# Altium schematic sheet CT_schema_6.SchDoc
size 296 x 239 mm
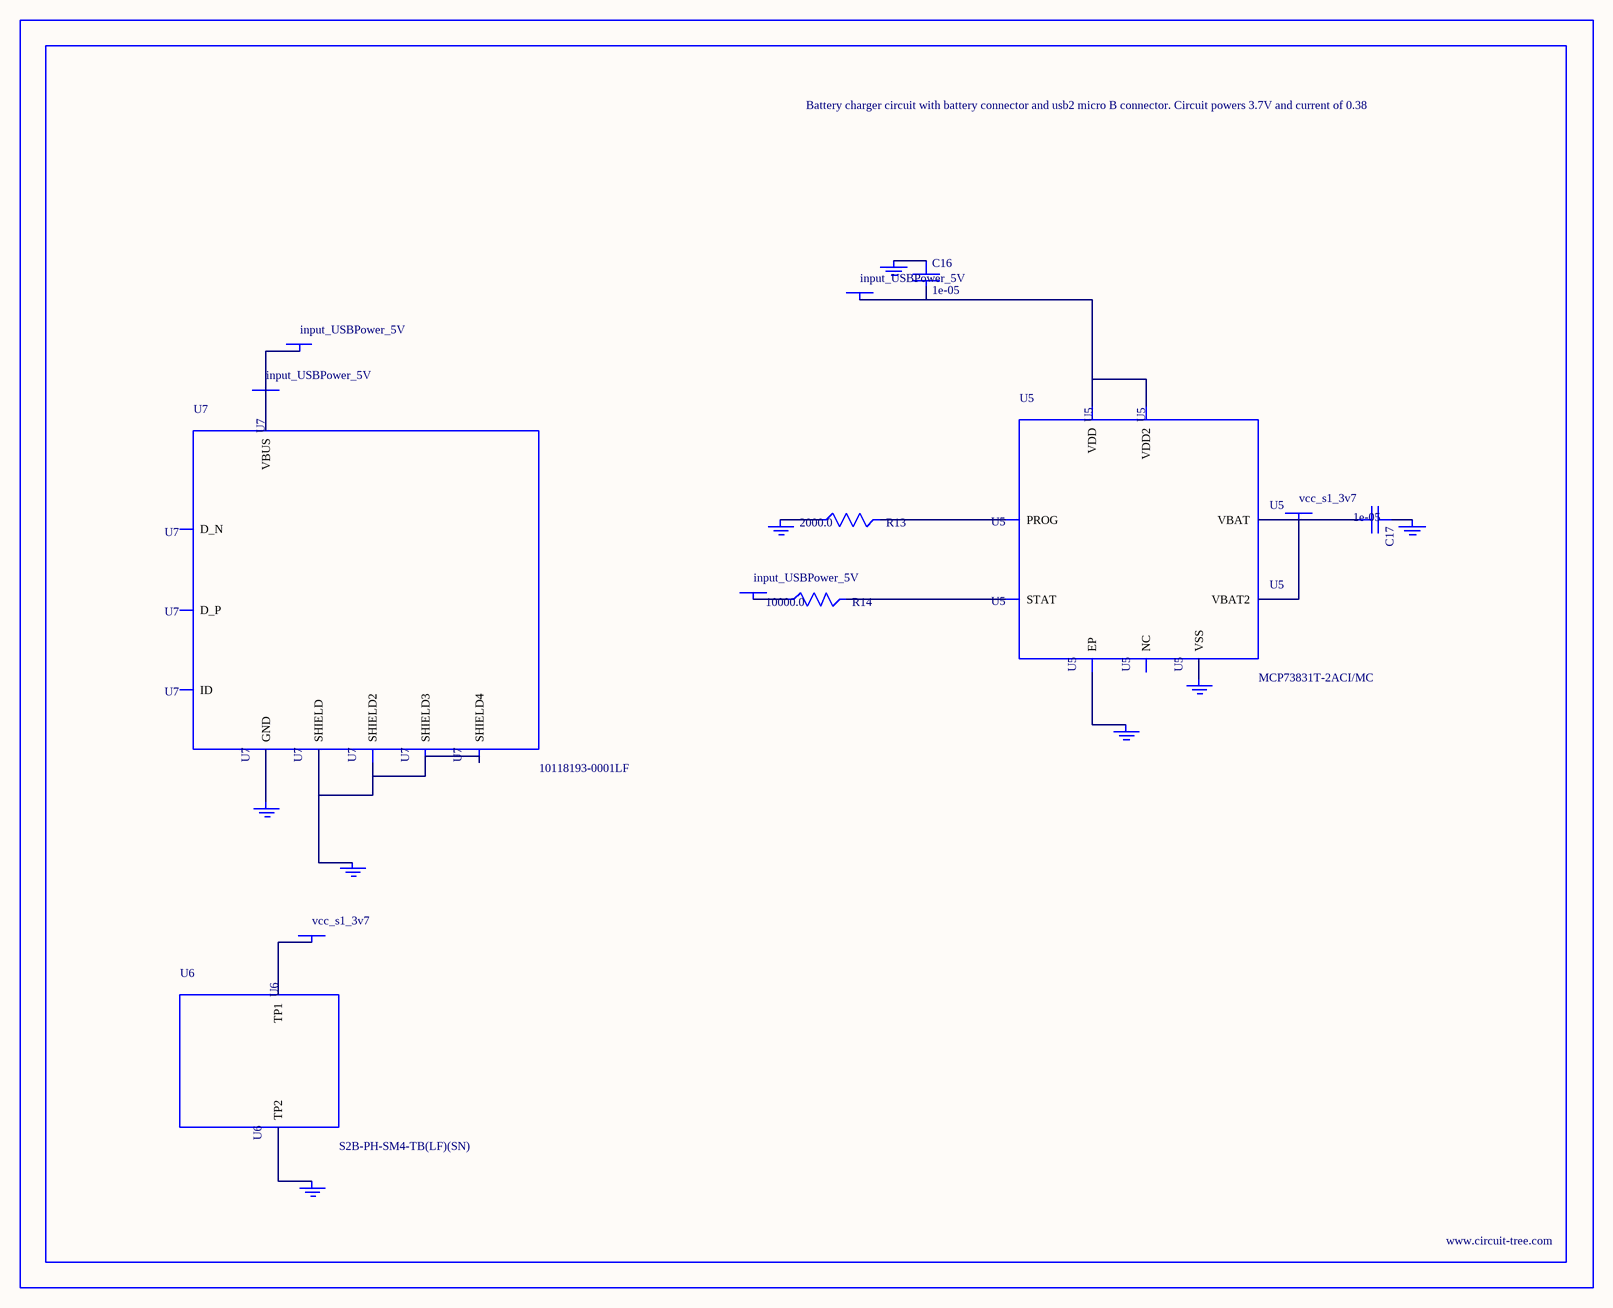
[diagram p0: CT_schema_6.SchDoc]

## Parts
BORDER5  (no value)
C16  1e-05  [C1206]
C17  1e-05  [C1206]
GND_INSTANCE_5_0  (no value)
GND_INSTANCE_5_1  (no value)
GND_INSTANCE_5_2  (no value)
GND_INSTANCE_5_3  (no value)
GND_INSTANCE_5_4  (no value)
GND_INSTANCE_5_5  (no value)
GND_INSTANCE_5_6  (no value)
GND_INSTANCE_5_7  (no value)
POWER_INSTANCE_5_0  input_USBPower_5V
POWER_INSTANCE_5_1  input_USBPower_5V
POWER_INSTANCE_5_2  vcc_s1_3v7
POWER_INSTANCE_5_3  vcc_s1_3v7
POWER_INSTANCE_5_4  input_USBPower_5V
POWER_INSTANCE_5_5  input_USBPower_5V
R13  2000.0  [R0603]
R14  10000.0  [R0603]
U5  MCP73831T-2ACI/MC  [DFN8_2X3MC]
U6  S2B-PH-SM4-TB(LF)(SN)  [JST-2-SMD]
U7  10118193-0001LF  [FCI_10118193-0001LF]

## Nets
NetC16_1: C16.1 GND_INSTANCE_5_0.0(GND)
NetC16_2: C16.2 POWER_INSTANCE_5_0.0(PWR) U5.1(VDD) U5.2(VDD2)
NetC17_1: C17.1 GND_INSTANCE_5_1.0(GND)
NetC17_2: C17.2 POWER_INSTANCE_5_2.0(PWR) U5.3(VBAT) U5.4(VBAT2)
NetGND_INSTANCE_5_2_0: GND_INSTANCE_5_2.0(GND) R13.1
NetGND_INSTANCE_5_3_0: GND_INSTANCE_5_3.0(GND) U5.9(EP)
NetGND_INSTANCE_5_4_0: GND_INSTANCE_5_4.0(GND) U5.6(VSS)
NetGND_INSTANCE_5_5_0: GND_INSTANCE_5_5.0(GND) U6.2(TP2)
NetGND_INSTANCE_5_6_0: GND_INSTANCE_5_6.0(GND) U7.6(SHIELD) U7.7(SHIELD2) U7.8(SHIELD3) U7.9(SHIELD4)
NetGND_INSTANCE_5_7_0: GND_INSTANCE_5_7.0(GND) U7.5(GND)
NetPOWER_INSTANCE_5_1_0: POWER_INSTANCE_5_1.0(PWR) R14.1
NetPOWER_INSTANCE_5_3_0: POWER_INSTANCE_5_3.0(PWR) U6.1(TP1)
NetPOWER_INSTANCE_5_4_0: POWER_INSTANCE_5_4.0(PWR) POWER_INSTANCE_5_5.0(PWR) U7.1(VBUS)
NetR13_2: R13.2 U5.8(PROG)
NetR14_2: R14.2 U5.5(STAT)

Not connected (* = marked no-connect by the designer): U5 7(NC); U7 2(D_N) 3(D_P) 4(ID)

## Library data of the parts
BORDER5 = BORDER_PAGE5
C16 C17 = C1206C106K3RACTU
GND_INSTANCE_5_0-GND_INSTANCE_5_7 = GND
POWER_INSTANCE_5_0-POWER_INSTANCE_5_5 = PWR
R13 = RC0603JR-072KL
R14 = RC0603JR-0710KL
